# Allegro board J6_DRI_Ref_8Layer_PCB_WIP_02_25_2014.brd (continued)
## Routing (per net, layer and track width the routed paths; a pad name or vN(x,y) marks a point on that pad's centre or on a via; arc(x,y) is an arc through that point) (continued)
VCC_SENSE: length 1.4
  TOP w0.254: v1(131.19,73.02) U45.B3
  BOTTOM w0.203: R549.2 131.19,72.33 v1(131.19,73.02)
VDD_???: length 1.1
  TOP w0.203: U45.L11 124.38,80.62 123.98,81.02 ; 132.78,73.02 132.38,73.42 U45.B1
VDD_CORE: length 41
  TOP w0.102: U52.H14 U52.H13 ; U52.T19 v1(65.53,55.65)
  TOP w0.127: U52.U9 U52.U8
  TOP w0.178: U52.L8 v1(69.55,64.47) U52.L7 ; U52.V8 v1(64.69,64.47) U52.U8 ; U52.N10 v1(68.75,62.83) ; U52.R16 v1(66.32,58.02) U52.T16 ; U52.N13 v1(67.94,59.67) U52.P13 ; U52.V16 v1(64.69,58.07) U52.U16 ; U52.H13 v1(71.91,60.45) ; U52.T13 v1(65.54,59.62) U52.U13 ; U52.J18 v1(71.15,56.44) U52.J17 ; v1(66.35,61.22) U52.R11 ; U52.T19 U52.R19
  TOP w0.203: U52.P12 v1(67.97,61.24) U52.P11 ; 128.78,80.22 U45.K6
  TOP w0.305: v2(65.91,77.24) C487.2 v2(65.91,74.81)
  TOP w1.016: L11.1 131.14,92.34 ; L11.1 129.74,91.26 ; L11.1 132.54,91.26 ; L11.1 131.14,90.18
  BOTTOM w0.203: v1(67.97,61.24) 68.41,60.8 68.81,60.8 C390.2 ; C386.2 67.01,61.88 v1(66.35,61.22) ; C363.2 68.75,62.21 v1(68.75,62.83) ; v1(69.55,64.47) 69.55,65.13 C364.2 ; v1(65.53,55.65) 65.46,55.58 C498.2 ; v1(64.69,64.47) 64.72,64.49 C388.2
  BOTTOM w0.305: v2(72.22,72.21) C456.2 v2(70.18,72.21) ; v2(66.4,72.21) C394.2 v2(64.31,72.21) ; v2(67.23,72.21) C393.2 v2(69.29,72.21) ; v2(75.27,72.21) C395.2 v2(73.22,72.21)
  BOTTOM w0.508: C326.2 131.14,93.07 ; C326.2 131.14,90.78 ; C326.2 132.92,91.93 ; C326.2 129.36,91.93
  vias: v2(129.49,95.2) v2(129.49,94.31) v2(129.49,93.42) v2(130.51,95.2) v2(130.51,94.31) v2(130.51,93.42) v2(132.03,95.2) v2(132.03,94.31) v2(132.03,93.42) v2(133.05,95.2) v2(133.05,94.31) v2(133.05,93.42) v2(133.17,91.26) v2(133.93,95.2) v2(133.93,94.31) v2(133.93,93.42)
VDD_DDR: length 305
  TOP w0.152: U52.AD26 v1(59.13,49.23) ; 61.13,51.25 v1(60.74,50.82) 61.13,50.45 ; U52.W16 v1(63.91,57.23) ; U52.G23 U52.G22 U52.H22
  TOP w0.178: U52.M20 v1(69.55,54.05) ; v1(69.55,54.05) U52.L20 ; v1(69.55,54.05) U52.L21 ; v1(69.55,54.05) U52.M21 ; v1(60.73,53.27) 61.13,52.85 U52.AA22 ; v1(60.73,53.27) U52.AC22 ; v1(60.73,53.27) 61.13,53.65 U52.AA21 ; v1(75.15,50.86) U52.E24 ; U52.H22 v1(71.96,53.27) U52.H21 72.39,53.71 72.39,54.4 U52.H20 ; U52.T24 v1(65.54,50.82) U52.T25
  TOP w0.203: 55.07,48.85 U52.AH27 ; U68.C1 78.23,29.07 v1(77.83,28.67) ; U52.AG20 56.73,54.05 55.83,54.05 55.66,53.89 ; U68.A9 v1(84.23,31.07) ; U65.H2 v1(30.28,27.29) ; v1(78.63,31.05) U68.A2
  TOP w0.229: U52.W27 63.12,48.45 63.12,47.54
  TOP w0.254: U65.C1 29.08,30.9 v1(29.48,31.3) ; v1(42.18,32.09) U66.B2 ; 56.21,46.31 v2(56.16,46.31) ; 56.21,46.31 C138.1 56.97,46.88 57.13,47.04 U52.AG28 ; 56.21,46.31 55.83,45.93 55.07,45.93 ; U69.M9 98.99,21.86 v1(99.39,21.46) 100.07,20.78 C190.1 ; v1(60.65,21.45) U67.M9 ; C559.1 v2(76.63,46.31) ; v2(69.22,26.29) 69.24,26.32 C631.1 ; U66.N9 48.58,23.29 v1(49.38,23.29) 50.72,23.29 C183.1 ; C165.2 v2(68.02,31.57) ; U67.K1 v1(53.45,23.05) ; C204.2 v2(46.69,16.94) ; U66.D2 v1(42.98,29.7) ; U65.H9 v1(35.88,27.29) ; U65.D9 v1(35.88,29.7) U65.E9 ; C162.1 v2(88.49,30.81) ; v1(29.48,25.69) U65.K2 ; U68.M1 v1(77.83,21.46) ; v2(66.75,15.7) C207.2 v2(65.68,14.76) ; v2(62.41,46.18) C139.1 63.2,46.81 63.02,46.99 63.02,47.44 63.12,47.54 ; U66.H9 v1(48.58,27.29) ; U66.C1 41.78,30.9 v1(41.38,31.3) ; U66.E9 v1(48.58,29.7) U66.D9 ; v1(99.39,23.06) 98.99,23.46 U69.K9 ; U69.K1 92.58,23.46 v1(92.18,23.06) ; v1(92.98,27.87) 93.38,27.47 U69.E2 ; U65.N9 35.88,23.29 v1(36.68,23.29) 38.02,23.29 C182.1 ; U65.C9 v1(35.88,30.5) ; v1(78.63,27.87) 79.03,27.47 U68.E2 ; v2(54.64,17.3) C214.1 ; U64.2 6.31,25.36 v2(6.3,25.35) ; C164.2 65.76,32.08 v2(65.89,31.96) ; U68.E9 v1(85.03,27.05) ; C199.1 78.56,19.69 v1(78.56,20.37) ; C137.1 54.18,48.85 v2(54.89,48.85) ; U65.G7 v1(33.48,28.09) ; U65.N1 v1(28.45,22.89) ; U67.G8 v1(59.85,25.47) ; U66.R1 v1(41.06,21.29) ; v2(84.28,17.78) 84.28,18.77 C195.1 ; v1(34.28,32.1) U65.A8 ; v1(98.59,25.46) 98.19,25.86 U69.G8 ; C180.2 v2(67.51,24.84) ; U68.K1 78.23,23.46 v1(77.83,23.06) ; U52.J27 71.93,48.45 71.93,47.7 72.16,47.48 v1(72.16,46.99) ; v1(28.55,32.89) 28.68,32.89 U65.A1 ; C562.1 v2(84.66,46.13) ; C159.1 98.58,31.28 v1(98.58,31.07) U69.A9 ; U67.D7 v1(59.05,28.67) ; v1(29.48,32.09) U65.B2 ; C193.1 38.11,20.89 v1(35.88,20.89) U65.R9 ; U69.D7 v1(97.78,27.87) ; C656.1 v2(76.3,44.91) ; U68.K9 84.64,23.46 v1(85.04,23.06) ; v1(47.78,32.9) U66.A8 ; U67.M1 v1(53.45,21.45) ; C213.1 v2(48.72,17.12) ; C169.1 76.4,29.03 76.77,28.67 v1(77.83,28.67) ; U67.C1 v1(53.45,29.47) ; C196.1 98.3,18.72 v2(98.3,17.78) ; v2(6.17,18.24) C201.2 v2(5.16,19.51) C191.2 v2(5.16,22.18) ; U65.K8 v1(35.08,25.69) ; C160.1 78.31,31.38 v1(78.63,31.05) ; U66.H2 v1(42.98,27.29) ; C181.2 v2(108.79,24.84) ; C211.1 v2(36.07,17.17) ; v1(41.38,32.89) U66.A1 ; C136.1 v2(62.26,44.15) ; C185.1 v2(88.72,22.3) ; 5.41,23.32 v2(6.17,23.32) ; U67.G2 v1(54.25,25.45) ; C205.2 v2(59.41,17.99) ; C176.2 v2(108.79,27.64) ; C548.1 72.82,44.15 v2(73,43.97) ; C210.1 v2(29.87,17.3) ; C208.2 v2(104.03,16.21) ; U67.A9 v1(60.65,31.07) ; C194.1 50.66,20.74 48.74,20.74 v1(48.58,20.89) U66.R9 ; U66.N1 v1(41.06,22.89) ; U69.M1 v1(92.18,21.46) ; v1(86.54,27.79) 86.64,27.69 C171.1 88.44,27.69 v2(88.52,27.76) ; C170.1 90.6,28.43 91.94,28.43 v1(92.18,28.67) 92.58,29.07 U69.C1 ; C184.1 74.6,22.56 v2(74.3,22.25) ; 55.66,53.89 54.91,53.89 v2(54.57,53.55) 54.09,53.55 54.06,53.57 C143.1 ; U66.C9 v1(48.58,30.5) ; C161.1 91.97,32.06 v1(92.98,31.05) U69.A2 ; v2(88.6,20.55) 88.87,20.27 C198.2 ; v2(42.57,17.17) C212.1 ; C203.2 v2(33.86,16.96) ; v1(41.38,28.9) U66.F1 ; C166.2 104.83,30.86 v2(104.52,31.17) ; U66.K8 v1(47.78,25.69) ; U69.G2 v1(92.98,25.47) ; v2(82.85,46.76) 82.85,46.79 82.58,46.51 C657.1 v2(82.58,44.33) ; U68.G8 83.84,25.86 v1(84.24,25.46) ; v2(74.19,19.76) C197.2 75.34,19.76 ; U69.E9 v1(99.39,27.05) ; v1(60.65,23.05) U67.K9 ; C655.1 v2(83.27,47.7) ; U66.G7 v1(46.18,28.09) ; C189.1 86.1,20.4 v1(85.04,21.46) 84.64,21.86 U68.M9 ; U67.B9 v1(60.65,30.27) ; C167.2 v2(109.98,21.11) ; U67.E9 v1(59.85,27.87) ; v2(81.99,48.83) C556.1 ; C557.1 50.75,43.18 50.24,43.69 v2(50.24,43.77) ; C584.1 v2(70.92,46.18) ; v1(28.68,28.9) U65.F1 ; U67.E2 v1(54.25,27.87) ; U67.A2 v1(54.25,31.07) ; U68.G2 v1(78.63,25.47) ; v1(42.18,25.69) U66.K2 ; C175.2 v2(67.51,27.64) ; U65.D2 v1(30.28,30.5) ; C200.1 92.94,19.59 v1(92.94,20.25) ; U69.B9 v1(99.39,29.47) ; 5.41,24.59 v2(6.17,24.59) ; v2(62.97,15.7) C206.2 v2(64.03,14.76) ; v1(84.23,31.07) 84.73,31.57 C158.1 ; U68.B9 v1(85.03,29.47) ; U65.R1 v1(28.36,21.29) ; C209.2 v2(107.8,16.21) ; C589.1 v2(84.71,48.67) ; U68.D7 v1(83.43,27.87)
  TOP w0.305: v2(54.89,48.85) 55.07,48.85 ; v1(100.79,28.15) C172.1 v2(102.77,28.15) ; v1(100.84,31.57) C163.1 v2(102.79,31.57)
  TOP w1.016: 113.5,81.49 L13.1 ; L13.1 114.5,82.81 ; L13.1 115.51,81.49 ; L13.1 114.5,80.16
  BOTTOM w0.203: U68.G2 v1(78.63,25.47) ; U68.G8 v1(84.24,25.46) ; U116.A2 v1(84.23,31.07) ; v1(77.83,30.27) U116.B9 ; v1(63.91,57.23) C508.1 ; U116.E2 v1(83.43,27.87) ; v1(92.98,31.05) U115.A9 ; v1(78.63,31.05) U116.A9 ; U115.E9 v1(92.98,27.87) 93.55,27.87 93.94,28.26 U115.D7 ; U69.K1 92.58,23.46 v1(92.18,23.06) ; v1(77.83,23.06) 78.23,23.46 U68.K1 ; C528.1 71.96,53.29 v1(71.96,53.27) ; U69.G8 v1(98.59,25.46) ; U116.D7 79.59,28.26 79.2,27.87 v1(78.63,27.87) U116.E9 ; U115.B9 v1(92.18,30.27) ; U69.M9 v1(99.39,21.46) ; v1(92.98,25.47) U69.G2 ; U116.C1 v1(85.03,29.47) ; v1(77.83,21.46) U68.M1 ; v1(73.53,51.64) C537.1 ; v1(98.58,31.07) U115.A2 ; U68.K9 v1(85.04,23.06) ; U115.E2 v1(97.78,27.87) ; v1(92.18,21.46) U69.M1 ; U115.C1 v1(99.39,29.47) ; U69.K9 v1(99.39,23.06) ; U68.M9 v1(85.04,21.46)
  BOTTOM w0.254: C644.1 91.11,21.67 91.32,21.46 v1(92.18,21.46) ; v1(35.88,27.29) 36.44,27.29 C622.1 ; v1(59.85,27.87) 60.02,27.87 C614.1 ; C563.1 50.24,43.46 v2(50.24,43.77) ; C671.1 v2(89.56,17.05) ; C666.1 v2(98.55,17.03) ; v2(99.82,13.59) C665.1 v2(99.82,16.03) ; v2(84.84,16.03) C673.1 v2(84.84,13.59) ; v1(35.88,30.5) 36.2,30.81 C598.1 ; C669.1 v2(94.11,17.03) ; C638.1 28.43,22.91 v1(28.45,22.89) ; v2(98.3,17.78) 98.3,18.8 C649.1 ; C679.1 v2(74.02,17.03) ; v1(48.58,29.7) 49.33,29.7 C610.1 ; v2(77.37,16.03) C678.1 v2(77.37,13.59) ; C611.1 35.97,29.61 v1(35.88,29.7) ; C624.1 33.48,27.57 v1(33.48,28.09) ; U116.E9 77.72,27.97 76.43,27.97 75.97,27.51 C616.1 ; C564.1 v2(61.24,42.6) ; C574.1 70.1,54.05 v1(69.55,54.05) ; C677.1 v2(78.82,17.05) ; C602.1 60.82,30.43 v1(60.65,30.27) ; C637.1 v1(86.51,24.34) ; C676.1 v2(80.34,17.07) ; C591.1 54.25,31.69 v1(54.25,31.07) ; v1(54.25,25.45) 54,25.45 53.54,25 C633.1 ; C668.1 v2(95.5,17.03) ; v1(48.58,30.5) 48.9,30.81 C597.1 ; C561.1 72.82,44.15 v2(73,43.97) ; C641.1 52.79,21.45 v1(53.45,21.45) ; C208.2 v2(104.03,16.21) ; C640.1 60.99,21.8 v1(60.65,21.45) ; C613.1 30.28,26.64 v1(30.28,27.29) ; C560.1 v2(47.8,54.51) ; C585.1 92.64,32.57 92.64,31.4 v1(92.98,31.05) ; C643.2 v2(67.51,22.05) ; v2(92.86,16.03) C670.1 v2(92.86,13.59) ; v1(29.48,32.09) 29.49,32.1 C583.1 ; C605.1 28.59,28.81 v1(28.68,28.9) ; C571.1 v2(58.09,41.99) ; U115.E9 92.02,28.02 90.88,28.02 90.37,27.51 C615.1 ; v1(48.58,27.29) 49.14,27.29 C621.1 ; v1(41.06,21.29) 40.42,21.29 C639.1 ; C176.2 v2(108.79,27.64) ; v1(59.85,25.47) 60.46,25.47 C632.1 ; v1(60.73,53.27) 61.48,53.27 C549.1 ; v2(84.28,17.78) 84.28,18.85 C650.1 ; C595.1 91.89,30.56 v1(92.18,30.27) ; v1(77.83,21.46) 76.99,21.46 76.78,21.67 C645.1 ; C651.2 v1(100.91,19.76) ; 52.73,29.42 52.78,29.47 v1(53.45,29.47) ; C590.1 60.86,31.28 v1(60.65,31.07) ; v1(75.15,50.86) 75.24,50.86 C541.1 ; C581.1 99.09,31.57 v1(98.58,31.07) ; v2(72.86,16) C630.1 v2(70.8,16) ; v2(62.97,15.7) C206.2 v2(64.03,14.76) ; C181.2 v2(108.79,24.84) ; C654.2 v2(68.15,17.86) ; C608.1 58.91,28.53 v1(59.05,28.67) ; v2(56.39,44.1) 55.98,44.51 C578.1 ; v2(55.96,40.46) C140.1 v2(57.35,41.48) ; C160.1 78.63,32.27 v1(78.63,31.05) ; C600.1 42.98,30.34 v1(42.98,29.7) ; C612.1 46.18,28.6 v1(46.18,28.09) 46.18,27.57 C623.1 ; v2(63.73,39.32) C576.1 v2(61.65,39.32) ; C674.1 v2(83.52,17.1) ; v1(84.23,31.07) 84.73,31.57 C158.1 ; C588.1 27.92,32.89 v1(28.55,32.89) ; C601.2 v2(108.23,29.01) ; C570.1 v2(50.24,40.67) ; C653.2 v2(109.45,17.86) ; C652.2 v2(88.47,19.76) ; v1(47.78,32.9) 47.78,33.47 C580.1 ; v1(34.28,32.1) 34.17,32.21 C594.1 ; C207.2 v2(66.75,15.7) ; C672.1 v2(88.04,17.05) ; v1(41.38,28.9) 40.6,28.9 C606.1 ; C667.1 v2(97.03,17.03) ; C162.1 v2(88.49,30.81) ; C664.1 v2(103.07,16.47) ; C675.1 v2(81.99,17.07) ; C175.2 v2(67.51,27.64) ; 55.66,35.03 v2(56.34,35.71) ; v2(61.42,36.65) 61.47,36.6 C577.1 63.91,36.6 v2(63.96,36.65) ; C592.1 v2(102.95,30.81) ; C599.2 v2(66.95,31.63) ; C587.1 40.74,32.89 v1(41.38,32.89) ; C180.2 v2(67.51,24.84) ; C569.1 v2(53.98,42.67) ; C572.1 v2(74.75,42.12) ; C609.1 54.25,27.87 v1(54.25,27.87) 54.25,27.26 C625.1 ; C209.2 v2(107.8,16.21) ; v1(77.83,30.27) 77.03,31.07 76.19,31.07 75.68,30.56 C596.1 ; C636.1 v1(100.89,24.34) ; C642.2 v2(108.79,22.05)
  BOTTOM w1.016: C350.2 113.84,83.19 ; C350.2 112.78,81.49 ; C350.2 113.84,79.78 ; C350.2 114.91,81.49
  vias: v2(112.22,83.64) v2(112.22,82.76) v2(112.22,81.49) v2(112.22,80.6) v2(112.22,79.83) v2(113.23,83.64) v2(114.25,83.64)
VDD_DSPEVE_IVA_GPU: length 73
  TOP w0.102: 64.33,61.68 U52.V11
  TOP w0.127: U52.J13 U52.K13
  TOP w0.178: U52.M12 U52.M11 U52.L11 ; U52.V11 U52.U11 U52.U12 ; U52.V14 v1(64.75,59.67) ; U52.V19 U52.V18 v1(64.72,56.44) U52.U18 65.13,55.85 65.11,55.83 65.11,55.48 65.13,55.46 U52.U19 ; v1(63.98,62.05) 64.33,61.68 ; v1(63.98,62.05) U52.V10 ; v1(63.98,62.05) U52.W10 ; v1(63.98,62.05) U52.W11 ; U52.W13 v1(63.14,59.62)
  TOP w0.203: U52.M10 U52.M11 ; U45.K2 131.98,80.22 ; U52.K12 v1(70.35,61.22) ; v1(70.35,61.22) U52.L12 ; v1(70.35,61.22) U52.K11 v1(71.17,62.05) U52.K10 ; v1(70.35,61.22) U52.L11 U52.L10 ; U52.L12 v1(69.55,60.45) ; U52.L12 U52.K13 ; v1(69.55,60.45) U52.M12 ; v1(69.55,60.45) U52.M13
  TOP w0.305: v2(75.76,74.37) C374.2 v2(77.81,74.37) ; v2(71.25,74.75) C453.2 v2(71.25,77.29) ; v2(80.59,66.49) C463.1 v2(80.59,68.04) ; v2(83.65,74.37) C90.2 v2(81.6,74.37) ; v2(50.75,67.4) C108.2 v2(50.75,65.34) ; v2(82.88,69.05) C105.2 v2(82.88,67) ; v2(57.54,74.37) C111.2 v2(55.38,74.37)
  TOP w1.016: L14.1 141.43,82.81 ; L14.1 140.42,81.49 ; L14.1 142.43,81.49 ; L14.1 141.43,80.16 ; L16.1 141.43,78.23 ; L16.1 140.42,76.91 ; L16.1 141.43,75.59 ; L16.1 142.43,76.91
  BOTTOM w0.102: 71.83,63.64 71.57,63.38 71.57,62.46 v1(71.17,62.05)
  BOTTOM w0.127: v1(63.14,59.62) 62.77,59.25 61.91,59.25 C112.1
  BOTTOM w0.203: C495.1 69.4,60.31 v1(69.55,60.45) ; v1(63.98,62.05) 63.98,62.71 C475.1 ; C466.1 64.7,59.62 v1(64.75,59.67) ; C469.1 70.35,60.66 v1(70.35,61.22)
  BOTTOM w0.305: v2(63.37,74.37) C478.2 v2(61.28,74.37) ; v2(58.36,74.37) C483.2 v2(60.41,74.37) ; v2(78.63,74.37) C373.2 v2(80.78,74.37) ; v2(80.59,64.02) C107.1 v2(80.59,65.67) ; v2(53.67,67.58) C473.1 v2(53.67,69.23) ; v2(80.59,70.5) C492.1 v2(80.59,68.85) ; v2(60.86,79.33) C460.1 v2(60.86,76.79) ; v2(82.88,63.77) C465.2 v2(82.88,65.93) ; v2(53.67,61.99) C474.1 v2(53.67,60.34) ; v2(53.67,71.59) C118.1 v2(53.67,70.04) ; v2(63.13,72.21) C372.1 v2(61.48,72.21) ; v2(57.24,72.21) C89.1 v2(55.69,72.21) ; v2(53.67,62.75) C119.1 v2(53.67,64.4)
  vias: v2(140.67,83.14) v2(140.92,79.2) v2(143.46,83.39) v2(143.46,82.5) v2(143.46,80.72) v2(143.46,79.83) v2(143.46,79.07) v2(143.46,78.18) v2(143.46,76.41) v2(143.46,75.39) v2(144.22,83.39) v2(144.22,82.5) v2(144.22,81.61) v2(144.22,80.72) v2(144.22,79.83) v2(144.22,79.07) v2(144.22,78.18) v2(144.22,77.29) v2(144.22,76.41) v2(144.22,75.39)
VDD_MPU: length 83
  TOP w0.102: U52.M15 v1(69.53,58.05) U52.L15 ; U52.L16 v1(69.53,57.25) ; v1(69.53,57.25) U52.M16 ; v1(69.53,57.25) U52.L17 ; v1(69.53,57.25) U52.M17 U52.N17 ; U52.N18 U52.M18 U52.L18
  TOP w0.203: v1(67.94,56.47) U52.N17 ; v1(67.94,56.47) U52.N18 ; v1(67.94,56.47) U52.P17 v1(67.16,56.47) ; v1(67.94,56.47) U52.P18 v1(67.16,56.47) ; v1(69.53,54.87) U52.L19 U52.L18 ; v1(70.35,56.49) 69.93,56.07 U52.L18 ; v1(70.35,56.49) U52.L17 69.53,56.5 ; v1(70.35,56.49) U52.K17 ; v1(70.35,56.49) U52.K18 ; U52.R18 v1(67.16,56.47) ; 69.53,56.5 U52.L18 ; 69.53,56.5 U52.M17
  TOP w0.254: U45.B13 122.78,73.42 v1(122.38,73.02)
  TOP w0.305: v2(90.51,58.5) C96.2 v2(88.46,58.5) ; v2(85.98,69.12) C360.2 v2(85.98,66.68) ; v2(82.37,51.88) C389.1 v2(82.37,53.43) ; v2(88.9,69.93) C356.1 v2(91.59,69.93) ; v2(85.41,58.5) C93.2 v2(87.46,58.5) ; v2(80.59,58.38) C370.2 v2(80.59,56.84) ; v2(80.59,51.88) C365.1 v2(80.59,53.43) ; v2(38.23,26.58) C366.1 v2(38.23,28.23) ; v2(84.65,54.05) C367.2 v2(86.7,54.05)
  TOP w1.016: 114.5,71.02 L17.1 ; L17.1 115.51,72.34 ; L17.1 114.5,73.66 ; L17.1 113.5,72.34 ; L15.1 115.51,76.91 ; L15.1 113.5,76.91 ; L15.1 114.5,75.59 ; L15.1 114.5,78.23
  L3-SIGNAL w0.102: v1(122.38,73.02) 121.23,71.87
  L3-SIGNAL w0.305: 121.23,71.87 120.82,71.45 117.3,71.45 116.79,70.94 v2(116.79,70.31)
  BOTTOM w0.203: v1(67.94,56.47) 68.28,56.14 C391.2 ; C384.1 69.6,57.99 v1(69.53,58.05) ; v1(67.16,56.47) 66.52,55.83 C368.2
  BOTTOM w0.254: v1(70.35,56.49) 70.33,56.47 C385.1
  BOTTOM w0.305: v2(112.09,71.2) 111.84,70.94 R554.1 ; v2(82.37,55.9) C392.2 v2(82.37,54.24) ; v2(82.88,61.86) C387.1 v2(82.88,60.21) ; v2(80.59,54.24) C396.1 v2(80.59,55.9) ; v2(88.46,65.1) C94.2 v2(90.51,65.1) ; v2(85.53,65.1) C92.2 v2(87.59,65.1) ; v2(90.53,62.18) C91.2 v2(88.46,62.18) ; v2(85.48,62.18) C95.2 v2(87.59,62.18) ; v2(84.59,56.97) C359.2 v2(82.44,56.97) ; v2(80.59,61.48) C369.1 v2(80.59,63.13)
  BOTTOM w1.016: 113.84,75.21 C378.2 ; C378.2 113.84,78.62 ; C378.2 114.91,76.91 ; C378.2 112.78,76.91 ; 112.78,72.34 C410.2 ; C410.2 113.84,70.64 ; C410.2 113.84,74.04 ; C410.2 114.91,72.34
  vias: v2(112.09,78.69) v2(112.09,77.55) v2(112.09,76.66) v2(112.09,75.77) v2(112.09,74.88) v2(112.09,73.99) v2(112.09,73.1) v2(112.09,72.09) v2(112.09,70.31) v2(112.09,69.42) v2(112.98,69.42) v2(113.11,74.63) v2(113.18,70.31) v2(113.87,69.42) v2(114.5,70.31) v2(114.88,69.42) v2(115.77,69.42)
VDD_RTC: length 4.9
  TOP w0.178: 61.13,58.45 v1(61.54,58.07)
  TOP w0.203: U45.A5 129.18,71.76 129.43,71.52
  TOP w0.381: C102.2 v2(130.76,69.8) 130.76,70.18 v1(129.74,71.2) 129.43,71.52
  vias: v2(129.74,67.01) v2(130.76,67.01) v2(131.78,67.01)
VDDA_ANA: length 1.7
  TOP w0.254: v1(126.38,74.62) U45.C8
  BOTTOM w0.305: C680.1 v1(126.38,74.62)
VDDA_DEBUG_1V8: length 1.1
  TOP w0.203: U52.N12 68.66,61.22 v1(68.66,61.29) 68.66,61.34 U52.N11
VDDA_HDMI: length 0.6
  TOP w0.178: v1(62.33,56.39) U52.Y17
VDDA_IVA_1V8: length 1.9
  TOP w0.178: U52.R17 v1(66.34,57.28)
  TOP w0.203: U52.R14 v1(67.16,58.83)
  BOTTOM w0.203: v1(67.16,58.83) 67.11,58.88 C497.1
VDDA_MPU_1V8: length 1.9
  TOP w0.203: U52.M14 v1(69.57,58.88) ; U52.N16 v1(68.73,58.07)
  BOTTOM w0.203: C507.2 68.58,57.91 v1(68.73,58.07)
VDDA_PCI_1P8: length 1.9
  TOP w0.178: v1(61.52,56.47) U52.AA17 U52.AA16 ; v1(63.14,58.85) U52.W14
VDDA_PHY_1V8: length 3.8
  TOP w0.178: U52.AA13 v1(61.53,60.46) 61.13,60.86 ; U52.W12 v1(63.14,60.43)
  TOP w0.254: v1(123.98,80.22) U45.K11
  BOTTOM w0.203: C486.1 61.67,60.6 v1(61.53,60.46)
  BOTTOM w0.254: C352.1 v1(123.98,80.22)
VDDA_PLL_1V8: length 7
  TOP w0.203: U45.B5 129.59,73.02 129.59,72.24 129.87,71.96 ; U52.AE16 v1(59.13,57.2) U52.AD16
  TOP w0.381: C103.2 v2(131.78,69.8) 131.78,70.44 v1(130.76,71.45) 130.25,71.96 129.87,71.96
VDDA_RTC: length 4.7
  TOP w0.178: 61.13,60.06 v1(61.54,59.65)
  TOP w0.203: U45.A8 126.75,72.58 126.75,72.04 127.33,71.45
  TOP w0.305: v2(127.71,69.8) 127.33,70.18 127.33,71.45
  TOP w0.381: C431.1 v2(127.71,69.8)
VDDA_SATA_1P8: length 0.5
  TOP w0.178: U52.V13 v1(63.96,59.67)
VDDA_VIDEO_1V8: length 1.7
  TOP w0.203: U52.P15 v1(67.13,58.1) U52.P16 ; U52.P14 v1(67.13,59.6)
VDDR_VREFSTL: length 94.8
  TOP w0.178: U65.M8 34.28,23.29 33.48,23.29 ; 29.72,26.5 30.05,26.5 30.05,26.49 31.08,26.49 ; 43.78,26.49 42.75,26.49 42.75,26.5 42.42,26.5 ; U52.N22 v1(68.69,53.27) ; U66.M8 46.98,23.29 46.18,23.29 ; v1(62.32,55.65) U52.Y18
  TOP w0.203: v1(29.48,27.29) U65.H1 29.48,26.49 29.71,26.49 29.72,26.5 ; U67.E1 v1(53.45,27.87) ; 42.42,26.5 42.41,26.49 42.18,26.49 U66.H1 v1(42.18,27.29)
  TOP w0.254: U67.J8 59.42,24.26 59.02,23.86 58.24,23.86 ; v1(84.24,23.86) 83.84,24.26 U68.J8 ; U69.E1 92.28,27.76 91.34,27.76 v1(91.08,27.51) ; v1(78.63,23.86) 78.63,23.86 78.63,24.46 78.44,24.66 77.17,24.66 ; C177.1 76.48,25.35 76.5,25.38 ; v1(92.98,23.86) 92.98,23.86 92.98,24.46 92.79,24.66 91.52,24.66 ; 56.01,26.26 54.41,26.26 54.25,26.42 54.25,27.06 U67.E1 ; U69.J8 98.19,24.26 v1(98.59,23.86) ; v1(76.73,27.51) 76.99,27.76 77.93,27.76 U68.E1 ; C197.1 76.23,18.24 ; C178.1 90.75,25.61 ; C198.1 90.88,18.75
  TOP w0.305: 67.59,42.88 v2(67.59,43.67)
  TOP w0.508: 58.24,23.86 56.92,23.86 ; 56.92,23.86 56.92,18.04 C205.1 56.97,14.68 ; 56.92,23.86 56.92,25.35 56.01,26.26 ; 32.41,23.29 33.48,23.29 ; 32.41,23.29 32.41,26.01 31.92,26.49 31.08,26.49 ; 32.41,23.29 32.41,18.06 C203.1 32.33,14.76 ; 45.11,23.29 46.18,23.29 ; 45.11,23.29 45.11,26.01 44.62,26.49 43.78,26.49 ; 45.11,23.29 45.11,18.04 C204.1 45.16,14.73
  L3-SIGNAL w0.254: v1(68.69,53.27) 68.29,52.86 67.74,52.86 67.47,52.59 67.47,49.09 68.02,48.54
  L3-SIGNAL w0.381: 68.02,48.54 68.02,44.5 67.59,44.07 v2(67.59,43.67)
  BOTTOM w0.203: U116.J8 v1(78.63,23.86) ; U115.J8 v1(92.98,23.86)
  BOTTOM w0.254: C629.1 86.39,25.35 85.69,24.66 84.43,24.66 84.23,24.46 84.23,23.86 v1(84.24,23.86) ; 100.04,24.66 98.78,24.66 98.58,24.46 98.58,23.86 v1(98.59,23.86) ; U115.E1 99.11,27.59 100.11,27.59 100.15,27.63 v1(100.15,27.61) ; v1(85.72,27.64) 84.81,27.64 U116.E1 ; C651.1 v2(100.91,18.24)
  BOTTOM w0.305: 49.93,55.88 C514.1 49.93,56.79 ; C617.1 v2(55.55,16.11) ; C618.1 43.51,15.95 v2(43.54,15.93)
  vias: v2(76.23,17.86) v2(76.23,17.1) v2(77.11,17.86) v2(77.11,17.1) v2(90.58,17.86) v2(90.58,17.1) v2(91.47,17.86) v2(91.47,17.1)
VDDS_1V8: length 45.7
  TOP w0.102: U52.N8 v1(68.73,63.66) ; v1(64.73,52.45) U52.V22 U52.V21 v1(63.93,54.05) U52.W21 U52.Y21 ; U52.AA19 61.93,55.56 61.93,56.05 U52.AA18
  TOP w0.127: U52.J22 71.55,53.09 71.55,53.64 U52.J21 ; U52.N8 U52.M8 ; U52.R8 U52.P8
  TOP w0.178: U52.M9 v1(69.55,63.65) U52.M8 ; v1(71.95,52.48) U52.J22 ; U52.W17 v1(63.93,56.44) U52.W18 ; U52.Y7 v1(62.33,65.24) ; U52.N21 v1(67.94,53.32) U52.P21 U52.P20 ; U52.AA7 v1(62.36,64.44) ; U52.G18 v1(72.72,56.44) U52.H17 v1(71.93,57.24) ; U52.R8 v1(66.34,63.65) U52.T8 ; v1(62.33,54.86) U52.AA19
  TOP w0.203: 126.38,79.42 126.78,79.02 U45.J8
  TOP w0.305: v2(55.24,79.15) C357.1 v2(55.24,76.71) ; v2(51.08,69.47) C406.1 v2(48.64,69.47) ; v2(51.13,59.95) C382.1 v2(48.59,59.95)
  TOP w0.381: R192.1 v2(123.14,67.01)
  TOP w1.016: L10.1 127.89,91.26 ; L10.1 126.57,92.27 ; L10.1 126.57,90.26 ; L10.1 125.25,91.26
  BOTTOM w0.102: C471.1 73.53,56.37 ; C400.2 61.13,65.51 61.13,65.09 61.37,64.85 61.94,64.85 v1(62.33,65.24) ; v1(62.36,64.44) 62,64.09 61.16,64.09 C399.2
  BOTTOM w0.203: C518.2 63.22,56.44 v1(63.93,56.44) ; v1(72.72,56.44) 73.46,56.44 73.53,56.37 ; v1(66.34,63.65) 65.63,62.94 C461.2 ; C524.1 68.02,53.39 v1(67.94,53.32) ; v1(64.73,52.45) 64.73,53.09 C530.1
  BOTTOM w0.305: v2(53.67,65.17) C371.1 v2(53.67,66.82)
  BOTTOM w0.508: 124.87,91.93 C327.2 ; C327.2 126.57,92.99 ; C327.2 126.57,90.86 ; C327.2 128.27,91.93
  vias: v2(124.54,91.26) v2(124.92,96.73) v2(124.92,95.71) v2(124.92,94.69) v2(124.92,93.68) v2(125.93,96.73) v2(125.93,95.71) v2(125.93,94.69) v2(125.93,93.68) v2(127.08,96.73) v2(127.08,95.71) v2(127.08,94.69) v2(127.08,93.68) v2(128.09,96.73) v2(128.09,95.71) v2(128.09,94.69) v2(128.09,93.68)
VDDSHV: length 39.9
  TOP w0.127: U52.H10 72.33,62.46 72.33,61.66 U52.H11 ; U52.P10 U52.R10 ; U52.J8 U52.K8
  TOP w0.152: U52.G15 U52.H15
  TOP w0.178: U52.R10 v1(66.37,62.08) ; U52.E22 v1(75.19,52.47) U52.D22 ; U52.T4 66.32,66.89 v1(66.32,66.88) U52.T5 ; U52.H8 72.33,63.83 72.33,63.83 72.33,63.52 72.33,63.52 U52.H9 v1(71.95,62.86) U52.H10 ; U52.C24 v1(76.75,50.85) ; v1(75.11,66.88) U52.E5 ; U52.H19 U52.H18 71.97,56.42 v1(71.96,56.42) ; U52.G5 v1(73.56,66.88) U52.G4 ; v1(59.14,66.85) U52.AD5 ; U52.N5 v1(68.72,66.89) U52.N4 ; U52.AD7 v1(59.09,65.24) U52.AE7 ; U52.W4 v1(63.92,66.89) U52.W5 ; U52.D16 v1(75.17,57.22) U52.E16 ; 61.13,64.86 v1(61.51,65.26) 61.13,65.66 ; U52.E10 v1(75.17,62.07) U52.D10 ; U52.U10 v1(64.72,62.08) ; v1(71.95,61.27) U52.H11 ; v1(75.13,68.48) U52.E3 ; v1(57.51,66.86) U52.AF5 ; U52.H16 v1(71.97,58.05) U52.H15 ; v1(66.34,65.26) U52.R7
  TOP w0.203: v1(77.5,66.07) 77.19,65.71 U52.B6 ; U52.B23 U52.C24
  BOTTOM w0.152: C449.1 61.9,66.35 61.9,65.64 v1(61.51,65.26) ; C464.1 59.09,65.52 v1(59.09,65.24)
  BOTTOM w0.203: C484.1 71.97,61.29 v1(71.95,61.27) ; v1(75.11,66.88) 75.11,66.91 C444.2 ; 75.26,61.42 75.17,61.51 v1(75.17,62.07) ; C455.2 77.55,66.12 v1(77.5,66.07) ; v1(63.92,66.89) 64.48,66.89 C443.1 ; v1(75.17,57.22) 75.26,57.13 75.26,56.47 ; C442.1 66.83,67.39 v1(66.32,66.88) ; v1(75.13,68.48) 75.13,68.79 C437.2 ; 69.42,67.26 C445.1 69.09,67.26 v1(68.72,66.89) ; v1(76.75,50.85) 77.39,50.85 C542.2 ; C458.2 74.24,66.19 v1(73.56,66.88) ; v1(57.51,66.86) 56.74,66.86 C454.1 ; v1(66.34,65.26) 66.91,65.26 C457.1 ; v1(75.19,52.47) 75.6,52.88 75.6,53.76 C526.1
  BOTTOM w0.254: C502.1 71.96,58.07 v1(71.97,58.05)
VDDSHV5: length 6.4
  TOP w0.178: U52.V12 v1(64.74,60.45)
  TOP w0.203: 128.78,70.89 128.78,73.03 128.38,73.42 U45.B6
  TOP w0.381: 128.78,70.89 129.74,69.93 v2(129.74,69.8) C101.1
  BOTTOM w0.254: C485.1 64.82,60.53 v1(64.74,60.45)
VDDSHV8: length 2.9
  TOP w0.178: U52.Y8 v1(63.11,63.64) U52.W8
  TOP w0.254: U45.C6 128.38,74.22 v1(128.78,73.82)
  BOTTOM w0.203: C467.1 62.74,63.11 62.74,63.27 v1(63.11,63.64)
H_DCAN1_RX: length 0.6
  TOP w0.102: v1(73.53,55.7) U52.G19
H_DCAN1_TX: length 0.6
  TOP w0.102: U52.G20 v1(72.71,54.85)
H_DDR1_A0: length 117.4
  TOP w0.102: v1(59.16,54.03) U52.AD20
  TOP w0.127: RN4.1 v1(62.39,24.14) ; TP1MC14.1 U67.K3 ; U66.N3 43.79,22.89 43.99,22.69 43.99,22.01 TP1MB19.1 ; TP1MA19.1 31.29,22.01 31.29,22.69 31.09,22.89 U65.N3
  L3-SIGNAL w0.114: TP1MA19.1 31.78,21.01 31.65,20.88 30.2,20.88 29.59,20.27 29.21,20.27 29.06,20.42 29.06,20.7 28.93,20.83 27.82,20.83 27.69,20.7 27.69,20.19 27.57,20.07 27.41,20.07 27.29,20.19 27.29,20.42 27.19,20.53 26.98,20.53 26.88,20.42 26.88,20.19 26.76,20.07 26.59,20.07 26.47,20.19 26.47,20.42 26.37,20.53 26.17,20.53 26.07,20.42 26.07,20.16 25.95,20.04 25.78,20.04 25.66,20.16 25.66,20.42 25.56,20.53 21.79,20.53 20.35,21.97 20.35,28.35 20.65,28.65 20.65,32.77 24.55,36.66 24.69,36.66 24.89,36.46 25.03,36.46 25.18,36.61 25.18,36.75 24.98,36.95 24.98,37.1 25.12,37.24 25.26,37.24 25.46,37.04 25.61,37.04 25.75,37.18 25.75,37.33 25.55,37.53 25.55,37.67 25.7,37.81 25.84,37.81 26.04,37.61 26.18,37.61 26.33,37.76 26.33,37.9 26.13,38.1 26.13,38.25 30.25,42.37 32.33,42.37 35.26,45.29 41.35,45.29 47.83,51.77 52.22,51.77 52.83,52.38 55.22,52.38 56.87,54.03 v1(59.16,54.03) ; v1(62.39,24.14) 60.91,22.67 58.08,22.67 57.69,23.05 TP1MC14.1 55.43,22.64 50.83,22.64 49.5,21.31 44.57,21.31 TP1MB19.1
  BOTTOM w0.127: TP1MA19.1 32.07,21.69 33.6,21.69 34.01,22.1 34.59,22.1 34.98,21.72 36.12,21.72 36.42,21.41 38.43,21.41 39.78,22.76 40.56,22.76 40.82,22.5 42.23,22.5 42.62,22.89 43.14,22.89 43.41,22.62 43.41,22.15 44.16,21.4 TP1MB19.1
H_DDR1_A1: length 113.7
  TOP w0.102: v1(59.93,54.79) U52.AC19
  TOP w0.127: RN4.2 v1(63.02,23.57) ; TP1MC16.1 U67.L7 ; TP1MA20.1 33.44,21.42 U65.P7 ; TP1MB20.1 46.14,21.42 U66.P7
  L3-SIGNAL w0.114: v1(63.02,23.57) 62.63,23.57 60.93,21.87 58.64,21.87 TP1MC16.1 54.2,22.25 53.82,21.87 51.86,21.87 50.5,20.51 46.4,20.51 TP1MB20.1 42.8,20.91 42.42,21.28 41.95,21.28 41.36,20.69 40.32,20.69 40.3,20.72 38.06,20.72 37.05,19.71 34.5,19.71 TP1MA20.1 32.79,20.4 30.4,20.4 29.69,19.69 25.04,19.69 24.93,19.8 24.93,19.94 24.8,20.07 24.6,20.07 24.47,19.94 24.47,19.8 24.36,19.69 24.12,19.69 24,19.8 24,19.93 23.89,20.04 23.66,20.04 23.55,19.93 23.55,19.8 23.43,19.69 23.2,19.69 23.09,19.8 23.09,19.93 22.97,20.04 22.75,20.04 22.63,19.93 22.63,19.8 22.52,19.69 22.05,19.69 19.96,21.77 19.96,32.59 30.12,42.75 32.08,42.75 35,45.67 41.1,45.67 47.57,52.15 52.04,52.15 52.58,52.68 55.04,52.68 56.69,54.33 58.7,54.33 59.15,54.79 v1(59.93,54.79)
H_DDR1_A2: length 122.7
  TOP w0.102: v1(60.71,54.86) U52.AC20
  TOP w0.127: U67.L3 56.31,21.8 56.31,19.41 TP1MC26.1 ; RN6.4 v1(63.02,19.07) ; U65.P3 30.91,21.87 30.91,21.87 31.18,21.6 31.18,20.82 31.6,20.4 31.6,19.7 31.48,19.59 TP1MA27.1 ; U66.P3 43.61,21.87 43.61,21.87 43.88,21.6 43.88,20.82 44.3,20.4 44.3,19.7 44.18,19.59 TP1MB27.1
  L3-SIGNAL w0.102: 60.33,54.2 60.33,53.84 60.07,53.58 59.72,53.58 59.48,53.34 59.48,53 59.31,52.84
  L3-SIGNAL w0.114: v2(21.74,21.54) 22.05,21.85 22.05,22 21.11,22.94 21.11,27.84 21.41,28.15 21.41,32.51 24.43,35.54 25.22,35.54 29.87,40.19 29.87,40.39 30.11,40.63 30.46,40.63 30.77,40.32 30.92,40.32 31.06,40.46 31.06,40.6 30.64,41.02 30.64,41.19 30.76,41.31 30.93,41.31 31.35,40.89 31.52,40.89 31.65,41.02 31.65,41.48 31.78,41.61 32.08,41.61 32.31,41.38 32.61,41.38 35.76,44.53 41.86,44.53 48.39,51.06 55.32,51.06 56.86,52.59 57.85,52.59 58.09,52.84 59.31,52.84 ; v1(60.71,54.86) 60.59,54.74 60.59,54.47 60.33,54.2 ; v1(63.02,19.07) 62.96,19 TP1MC26.1 54.59,19 53.99,18.4 45.21,18.4 45.11,18.49 TP1MB27.1
  BOTTOM w0.127: TP1MB27.1 43.37,17.68 39.83,17.68 39.7,17.81 39.21,17.81 39.08,17.68 35.66,17.68 35.53,17.55 35.53,17.45 35.41,17.33 34.62,17.33 34.49,17.45 34.49,17.55 34.37,17.68 33.07,17.68 32.96,17.78 32.96,17.94 32.84,18.06 32.68,18.06 32.56,17.94 32.56,17.78 32.46,17.68 32.13,17.68 32,17.81 32,18.37 31.88,18.49 TP1MA27.1 30.82,17.83 24.56,17.83 21.74,20.65 v2(21.74,21.54)
H_DDR1_A3: length 128.9
  TOP w0.102: v1(61.53,54.83) 61.13,55.25
  TOP w0.127: TP1MC13.1 U67.K2 ; TP1MA14.1 29.76,22.49 29.57,22.3 29.41,22.3 29.27,22.44 29.27,22.58 29.58,22.89 U65.N2 ; TP1MB14.1 42.46,22.49 42.27,22.3 42.11,22.3 41.97,22.44 41.97,22.58 42.28,22.89 U66.N2
  L3-SIGNAL w0.114: v1(63.02,24.56) 61.95,24.56 60.83,23.45 54.64,23.45 TP1MC13.1 53.86,23.44 52.01,23.44 51.66,23.09 50.88,23.09 50.12,22.34 49.08,22.34 48.85,22.11 45.4,22.11 44.7,22.81 43.7,22.81 43.38,22.49 TP1MB14.1 42.74,22.74 41.51,22.74 41.28,22.51 40.67,22.51 40.49,22.68 40.49,22.94 40.18,23.24 37.8,23.24 37.59,23.04 37.59,22.58 37.39,22.38 36.35,22.38 36.04,22.08 35.46,22.08 35.03,22.51 33.72,22.51 33.36,22.15 32.87,22.15 32.11,22.91 31.06,22.91 30.64,22.49 TP1MA14.1 29.83,22.49 29.73,22.39 29.73,21.77 29.63,21.67 29.42,21.67 29.32,21.77 29.32,22.39 29.22,22.49 28.14,22.49 27.95,22.68 26.87,22.68 26.75,22.56 26.75,21.54 26.62,21.41 26.39,21.41 26.31,21.49 26.31,22.31 26.2,22.43 26.03,22.43 25.91,22.31 25.91,21.52 25.81,21.41 25.6,21.41 25.5,21.52 25.5,21.95 25.4,22.05 25.2,22.05 25.1,21.95 25.1,21.52 24.99,21.41 24.71,21.41 24.46,21.67 24.46,21.92 24.84,22.3 24.84,23.07 24.71,23.19 23.7,23.19 23.57,23.07 23.57,22.68 23.7,22.56 v2(24.28,22.56)
  BOTTOM w0.102: v1(61.53,54.83) 61.09,55.27 60.6,55.27 60.38,55.5 60.38,55.81 60.12,56.06 59.77,56.06
  BOTTOM w0.127: 59.77,56.06 59.54,55.83 59.54,55.4 58.47,54.33 56.87,54.33 55.41,52.87 49.84,52.87 44.92,47.96 39.57,47.96 39.32,48.21 35.84,48.21 24.28,36.65 24.28,30.53 24.18,30.43 22.94,30.43 22.68,30.69 22.68,31.07 22.56,31.19 21.92,31.19 21.79,31.07 21.79,30.46 21.89,30.36 22.31,30.36 22.43,30.24 22.43,30.07 22.31,29.95 21.89,29.95 21.79,29.85 21.79,29.64 21.89,29.54 22.44,29.54 22.56,29.42 22.56,29.26 22.44,29.14 21.89,29.14 21.79,29.03 21.79,26.88 21.67,26.75 21.35,26.75 21.23,26.64 21.23,26.48 21.35,26.37 21.67,26.37 22.05,25.99 22.3,25.99 22.43,26.11 22.43,26.65 22.56,26.77 22.77,26.77 22.89,26.65 22.89,25.78 23.19,25.48 23.44,25.48 23.57,25.35 23.57,25.1 24.28,24.39 v2(24.28,22.56) ; RN15.4 63.9,24.14 63.47,24.56 v1(63.02,24.56)
H_DDR1_A4: length 129.5
  TOP w0.102: v1(57.53,53.3) U52.AF21
  TOP w0.127: TP1MB16.1 48.98,21.69 47.78,21.69 U66.P8 ; RN4.3 61.8,23.07 60.99,22.25 TP1MC17.1 U67.L8 ; TP1MA16.1 36.28,21.69 35.08,21.69 U65.P8
  BOTTOM w0.127: TP1MC17.1 58.64,22.66 57.45,22.66 57.3,22.51 57.3,21.79 57.18,21.67 57.02,21.67 56.9,21.79 56.9,22.51 56.78,22.63 56.61,22.63 56.49,22.51 56.49,21.86 56.37,21.74 56.2,21.74 56.08,21.86 56.08,22.15 55.98,22.25 55.78,22.25 55.68,22.15 55.68,21.86 55.56,21.74 55.39,21.74 55.27,21.86 55.27,22.15 55.17,22.25 54.97,22.25 54.87,22.15 54.87,21.84 54.75,21.72 54.58,21.72 54.46,21.84 54.46,22.15 54.36,22.25 54.15,22.25 54.05,22.15 54.05,21.97 53.94,21.86 53.15,21.86 52.81,22.2 50.24,22.2 49.99,21.95 TP1MB16.1 48.96,21.67 48.13,21.67 47.68,22.13 46.43,22.13 46.25,21.95 44.2,21.95 43.84,22.3 43.84,22.79 43.35,23.28 42.37,23.28 42.19,23.09 41.53,23.09 41.33,23.29 39.78,23.29 38.25,21.77 37.24,21.77 37.06,21.95 TP1MA16.1 36.39,22.1 35.51,22.1 35.13,22.48 33.79,22.48 33.43,22.13 32.51,22.13 32.33,22.3 32.33,22.55 31.6,23.28 31.45,23.28 31.24,23.07 31.06,23.07 30.85,23.28 29.62,23.28 29.29,22.94 28.96,22.94 28.78,23.12 28.78,23.4 28.6,23.57 25.86,23.57 25.74,23.69 25.74,23.84 25.86,23.95 26.62,23.95 26.74,24.07 26.74,24.22 26.62,24.34 25.86,24.34 25.73,24.46 25.73,24.97 25.6,25.1 25.22,25.1 25.1,25.22 25.1,25.37 24.99,25.47 24.82,25.47 24.71,25.57 24.71,25.77 24.82,25.87 24.99,25.87 25.1,25.98 25.1,26.18 24.99,26.28 24.82,26.28 24.71,26.38 24.71,26.59 24.82,26.69 24.99,26.69 25.1,26.79 25.1,26.99 24.99,27.09 24.82,27.09 24.71,27.2 24.71,27.4 24.82,27.5 24.99,27.5 25.1,27.6 25.1,27.84 24.97,27.97 24.84,27.97 24.71,28.09 24.71,28.78 24.84,28.91 25.32,28.91 25.81,29.39 25.81,35.59 25.98,35.77 26.24,35.77 26.75,36.27 26.75,36.53 26.62,36.65 26.62,37.01 30.53,40.92 30.73,40.92 31.32,40.34 31.57,40.34 31.76,40.53 31.76,40.67 31.41,41.02 31.41,41.17 31.55,41.31 31.7,41.31 32.05,40.96 32.19,40.96 32.33,41.1 32.97,41.1 33.1,41.23 33.1,42.62 33.4,42.93 33.4,43.32 33.95,43.87 33.95,44.25 34.05,44.35 34.25,44.35 34.35,44.25 34.35,43.63 34.47,43.51 34.64,43.51 34.76,43.63 34.76,44.54 34.88,44.66 35.05,44.66 35.16,44.54 35.16,43.63 35.28,43.51 35.45,43.51 35.57,43.63 35.57,44.54 35.69,44.66 35.86,44.66 35.98,44.54 35.98,43.63 36.1,43.51 36.26,43.51 36.38,43.63 36.38,44.54 36.5,44.66 36.67,44.66 36.79,44.54 36.79,43.63 36.91,43.51 37.08,43.51 37.2,43.63 37.2,44.54 37.32,44.66 37.48,44.66 37.6,44.54 37.6,43.63 37.72,43.51 37.89,43.51 38.01,43.63 38.01,44.54 38.13,44.66 38.3,44.66 38.42,44.54 38.42,43.63 38.53,43.51 38.7,43.51 38.82,43.63 38.82,44.54 38.94,44.66 39.11,44.66 39.23,44.54 39.23,43.64 39.36,43.51 39.6,43.51 39.72,43.39 39.72,43.17 39.84,43.06 40.01,43.06 40.13,43.17 40.13,44.16 40.25,44.27 40.42,44.27 40.54,44.16 40.54,43.12 40.66,43 40.82,43 40.94,43.12 40.94,44.16 41.06,44.27 41.23,44.27 41.35,44.16 41.35,43.61 41.45,43.51 41.65,43.51 41.95,43.81 42.43,43.81 50.06,51.44 53.43,51.44 53.84,51.84 55.6,51.84 57.06,53.3 v1(57.53,53.3)
H_DDR1_A5: length 138.1
  TOP w0.127: U65.P2 29.76,21.97 29.46,21.97 29.34,21.84 29.34,21.66 29.49,21.5 29.49,20.9 TP1MA21.1 28.64,20.89 28.14,20.4 28.14,19.21 28.03,19.1 27.87,19.1 27.76,19.21 27.76,20.55 27.66,20.65 27.48,20.65 27.38,20.55 27.38,19.23 27.28,19.13 27.1,19.13 27,19.23 27,20.24 26.9,20.35 26.7,20.35 26.59,20.24 26.59,19.74 26.49,19.64 26.29,19.64 26.19,19.74 26.19,20.24 26.09,20.35 25.34,20.35 25.22,20.46 25.22,20.63 25.34,20.75 26.59,20.75 26.7,20.85 26.7,21.06 26.59,21.16 25.34,21.16 25.22,21.28 25.22,21.45 25.34,21.56 26.59,21.56 26.7,21.67 26.7,21.87 26.59,21.97 25.34,21.97 25.22,22.09 25.22,22.26 25.34,22.38 26.59,22.38 26.7,22.48 26.7,22.99 26.11,23.57 26.11,24.11 26.01,24.21 24.95,24.21 24.84,24.32 24.84,24.48 24.95,24.59 26.01,24.59 26.11,24.69 26.11,24.87 26.01,24.97 25.07,24.97 24.97,25.07 24.97,25.25 25.07,25.35 26.01,25.35 26.11,25.45 26.11,25.63 26.01,25.73 25.02,25.73 24.92,25.83 24.92,30.61 24.21,31.32 24.21,32.06 24.1,32.16 23.8,32.16 23.7,32.26 23.7,32.47 23.8,32.57 24.1,32.57 24.21,32.67 24.21,33.69 24.1,33.79 23.82,33.79 23.7,33.91 23.7,34.08 23.82,34.2 24.1,34.2 24.21,34.3 24.21,34.5 24.1,34.6 23.82,34.6 23.7,34.72 23.7,34.89 23.82,35.01 24.1,35.01 24.21,35.11 24.21,35.34 24.1,35.44 23.82,35.44 23.7,35.56 23.7,35.73 23.82,35.85 24.1,35.85 24.21,35.95 24.21,36.65 30.05,42.5 31.03,42.5 31.13,42.6 31.13,43.54 31.23,43.64 31.44,43.64 31.54,43.54 31.54,42.62 31.66,42.5 31.83,42.5 31.95,42.62 31.95,43.87 32.25,44.16 32.25,44.3 32.06,44.49 32.06,44.63 32.2,44.78 32.34,44.78 32.63,44.49 32.8,44.49 32.92,44.61 32.92,44.78 32.63,45.06 32.63,45.21 32.78,45.35 32.92,45.35 33.11,45.16 33.25,45.16 33.51,45.42 33.99,45.42 34.09,45.52 34.09,45.81 34.21,45.93 34.38,45.93 34.5,45.81 34.5,45.52 34.6,45.42 34.8,45.42 34.9,45.52 34.9,45.81 35.02,45.93 35.19,45.93 35.31,45.81 35.31,45.52 35.41,45.42 35.61,45.42 35.72,45.52 35.72,45.81 35.83,45.93 36,45.93 36.12,45.81 36.12,45.52 36.22,45.42 36.43,45.42 36.53,45.52 36.53,45.81 36.65,45.93 36.82,45.93 36.93,45.81 36.93,45.52 37.04,45.42 37.24,45.42 37.34,45.52 37.34,45.81 37.46,45.93 37.63,45.93 37.75,45.81 37.75,45.52 37.85,45.42 38.05,45.42 38.15,45.52 38.15,45.81 38.27,45.93 38.44,45.93 38.56,45.81 38.56,45.52 38.66,45.42 38.87,45.42 38.97,45.52 38.97,45.81 39.09,45.93 39.25,45.93 39.37,45.81 39.37,45.52 39.47,45.42 39.68,45.42 39.78,45.52 39.78,45.81 39.9,45.93 40.07,45.93 40.19,45.81 40.19,45.52 40.29,45.42 40.49,45.42 40.59,45.52 40.59,45.93 40.71,46.05 40.88,46.05 41,45.93 41,45.31 41.12,45.19 41.29,45.19 41.41,45.31 41.41,45.95 41.51,46.05 41.71,46.05 41.81,45.95 41.81,45.52 41.91,45.42 42.57,45.42 49.71,52.56 55.6,52.56 55.9,52.85 U52.AH22 ; TP1MC18.1 54.25,22.26 U67.L2 ; U66.P2 42.46,21.97 42.16,21.97 42.04,21.84 42.04,21.66 42.19,21.5 42.19,20.9 TP1MB21.1 ; RN4.4 v1(63.02,22.5)
  L3-SIGNAL w0.114: v1(63.02,22.5) 62.32,22.5 60.89,21.07 57.68,21.07 56.9,21.84 54.63,21.84 TP1MC18.1 53.85,21.06 51.59,21.06 50.23,19.71 46.77,19.71 45.97,20.5 42.58,20.5 TP1MB21.1
  BOTTOM w0.127: TP1MB21.1 41.88,20.6 41.88,20.02 41.57,19.7 40.96,19.7 40.61,20.04 39.22,20.04 38.96,20.3 37.49,20.3 37.36,20.42 36.98,20.42 36.75,20.2 36.4,20.2 36.11,20.49 35.55,20.49 35.26,20.78 34.49,20.78 34.23,20.51 31.56,20.51 31.18,20.89 30.57,20.89 30.28,21.19 29.78,21.19 TP1MA21.1
H_DDR1_A6: length 129.2
  TOP w0.127: TP1MC21.1 U67.M8 ; v1(27.58,21.29) 27.58,21.91 27.48,22.01 27.23,22.01 27.13,22.11 27.13,22.32 27.23,22.42 27.48,22.42 27.58,22.52 27.58,23.34 27.69,23.44 28.04,23.44 28.14,23.54 28.14,23.75 28.04,23.85 27.69,23.85 27.58,23.95 27.58,24.15 27.69,24.26 28.04,24.26 28.14,24.36 28.14,24.56 28.04,24.66 27.69,24.66 27.58,24.76 27.58,24.97 27.69,25.07 28.15,25.07 28.27,25.19 28.27,25.36 28.15,25.47 27.69,25.47 27.58,25.58 27.58,25.78 27.69,25.88 28.15,25.88 28.27,26 28.27,26.17 28.15,26.29 27.69,26.29 27.58,26.39 27.58,26.62 27.41,26.8 27.41,26.94 27.54,27.08 27.54,27.22 27.4,27.37 27.25,27.37 27.12,27.23 26.82,27.23 26.04,28.02 26.04,34.55 26.86,35.37 26.86,35.52 26.26,36.12 26.26,36.29 26.37,36.41 26.54,36.41 27.26,35.69 27.43,35.69 27.55,35.81 27.55,35.98 26.75,36.77 26.75,36.92 26.9,37.06 27.04,37.06 27.72,36.38 27.87,36.38 28.01,36.52 28.01,36.67 27.33,37.35 27.33,37.49 27.47,37.64 27.62,37.64 28.41,36.84 28.58,36.84 28.7,36.96 28.7,37.13 27.9,37.92 27.9,38.07 28.05,38.21 28.19,38.21 28.87,37.53 29.02,37.53 29.16,37.67 29.16,37.82 28.48,38.5 28.48,38.64 28.62,38.79 28.77,38.79 29.63,37.93 29.8,37.93 29.91,38.05 29.91,38.21 29.05,39.07 29.05,39.22 29.2,39.36 29.34,39.36 30.02,38.68 30.17,38.68 30.31,38.82 30.31,38.97 29.63,39.65 29.63,39.79 29.77,39.94 29.92,39.94 30.84,39.01 31.01,39.01 31.13,39.13 31.13,39.3 30.2,40.22 30.2,40.37 30.35,40.51 30.49,40.51 31.23,39.78 31.39,39.78 31.51,39.9 31.51,40.07 30.78,40.8 30.78,40.94 30.92,41.09 31.07,41.09 31.94,40.21 32.84,40.21 33.86,41.23 38.43,41.23 38.81,40.85 39.52,40.85 47.09,48.41 47.23,48.41 47.37,48.28 47.51,48.28 47.66,48.42 47.66,48.56 47.52,48.7 47.52,48.84 47.66,48.99 47.81,48.99 47.94,48.85 48.09,48.85 48.23,48.99 48.23,49.14 48.09,49.27 48.09,49.42 48.24,49.56 48.38,49.56 48.52,49.43 48.66,49.43 48.81,49.57 48.81,49.71 48.67,49.85 48.67,49.99 48.81,50.14 48.96,50.14 49.09,50 49.24,50 49.38,50.14 49.38,50.29 49.24,50.42 49.24,50.57 49.56,50.88 49.93,50.88 50.04,50.98 50.04,51.16 50.14,51.26 50.34,51.26 50.44,51.16 50.44,50.98 50.54,50.88 50.75,50.88 50.85,50.98 50.85,51.16 50.95,51.26 51.15,51.26 51.25,51.16 51.25,50.98 51.36,50.88 51.56,50.88 51.66,50.98 51.66,51.16 51.76,51.26 51.97,51.26 52.07,51.16 52.07,50.98 52.19,50.85 53.74,50.85 54.35,51.46 55.8,51.46 55.98,51.64 56.72,51.64 U52.AG23 ; U66.R8 47.78,20.89 TP1MB22.1 ; U65.R8 35.08,20.89 TP1MA22.1
  BOTTOM w0.127: RN17.3 63.58,20.14 63.18,20.54 62.83,20.54 62.46,20.17 60.33,20.17 TP1MC21.1 58.01,20.41 57.79,20.41 57.69,20.31 57.69,19.97 57.59,19.87 57.39,19.87 57.29,19.97 57.29,20.31 57.19,20.41 56.98,20.41 56.88,20.31 56.88,19.97 56.78,19.87 56.58,19.87 56.47,19.97 56.47,20.31 56.37,20.41 55.66,20.41 55.3,20.04 54.71,20.04 54.51,20.25 54.08,20.25 53.63,19.8 53.12,19.8 52.83,20.09 52.63,20.09 52.53,19.99 52.53,19.81 52.43,19.71 52.22,19.71 52.12,19.81 52.12,19.99 52.02,20.09 49.15,20.09 48.74,19.69 48.19,19.69 TP1MB22.1 47.17,20.7 46.46,20.7 46.27,20.51 45.2,20.51 45.09,20.4 42.98,20.4 41.94,19.36 40.08,19.36 39.67,19.76 39.32,19.76 39.04,19.48 38.61,19.48 38.28,19.81 37.49,19.81 37.11,19.43 35.28,19.43 35.08,19.63 TP1MA22.1 34.57,20.09 34.47,20.2 33.12,20.2 32.99,20.07 31.52,20.07 31.12,20.47 29.13,20.47 28.93,20.68 28.2,20.68 v1(27.58,21.29)
H_DDR1_A7: length 107.9
  TOP w0.102: v1(59.1,53.24) U52.AE21
  TOP w0.127: U66.R2 TP1MB17.1 ; U67.M2 55.05,21.46 TP1MC22.1 ; RN6.2 v1(63.02,20.14) ; U65.R2 TP1MA17.1
  L3-SIGNAL w0.114: TP1MC22.1 56.31,20.65 57.5,19.47 60.99,19.47 61.67,20.14 v1(63.02,20.14)
  BOTTOM w0.127: TP1MC22.1 54.01,20.65 53.61,20.25 53.24,20.25 52.97,20.51 50.46,20.51 50.36,20.61 50.36,21.04 50.24,21.16 50.07,21.16 49.95,21.04 49.95,20.61 49.85,20.51 49.65,20.51 49.55,20.61 49.55,20.83 49.45,20.93 49.24,20.93 49.14,20.83 49.14,20.61 49.03,20.5 48.11,20.5 47.42,21.19 46.53,21.19 46.15,21.57 45.57,21.57 44.91,20.91 43.77,20.91 TP1MB17.1 42.7,21.41 42.42,21.41 42.09,21.74 41.73,21.74 41.53,21.54 41.53,21.03 41.07,20.58 39.4,20.58 39.17,20.8 36.54,20.8 36.05,21.29 35.45,21.29 35.35,21.19 34.29,21.19 34.16,21.06 33.81,21.06 33.54,21.33 32.85,21.33 32.46,20.93 31.6,20.93 31.23,21.3 30.68,21.3 TP1MA17.1 30.05,21.92 29.64,21.92 29.33,21.61 29.33,21.39 29.23,21.29 29.03,21.29 28.93,21.39 28.93,21.61 28.84,21.69 28.07,21.69 27.91,21.85 25.61,21.85 24.79,22.66 24.79,24.39 23.95,25.22 23.95,25.73 23.32,26.37 23.32,27 22.81,27.51 22.81,28.02 23.44,28.65 23.83,28.65 23.95,28.78 23.95,29.54 24.08,29.67 24.97,29.67 25.04,29.75 25.04,36.4 30.53,41.89 31.09,41.89 31.82,42.62 31.82,43.17 34.19,45.54 34.75,45.54 35.89,46.69 36.64,46.69 36.88,46.92 38.32,46.92 38.89,46.35 42.57,46.35 42.77,46.15 43.91,46.15 50.11,52.35 55.61,52.35 57.01,53.75 58.58,53.75 v1(59.1,53.24)
H_DDR1_A8: length 116.1
  TOP w0.102: U52.AF22 v1(58.34,53.23)
  TOP w0.127: TP1MC25.1 59.45,20.26 U67.N8 ; U65.T8 TP1MA26.1 ; U66.T8 TP1MB26.1
  L3-SIGNAL w0.102: 56.63,52.92 57.69,52.92 58,53.23 v1(58.34,53.23)
  L3-SIGNAL w0.114: 56.63,52.92 55.09,51.39 48.08,51.39 41.61,44.91 35.51,44.91 32.59,41.99 30.86,41.99 30.41,41.54 30.25,41.54 30.17,41.62 30.01,41.62 29.85,41.46 29.85,41.29 29.92,41.21 29.92,41.05 29.75,40.88 29.59,40.88 29.53,40.94 29.38,40.94 29.24,40.8 29.24,40.65 29.41,40.48 29.41,40.34 29.27,40.19 29.12,40.19 28.95,40.37 28.81,40.37 28.66,40.22 28.66,40.08 28.84,39.9 28.84,39.76 28.69,39.62 28.55,39.62 28.38,39.79 28.23,39.79 28.09,39.65 28.09,39.5 28.26,39.33 28.26,39.19 28.12,39.04 27.97,39.04 27.8,39.22 27.66,39.22 27.51,39.07 27.51,38.93 27.69,38.75 27.69,38.61 27.54,38.47 27.4,38.47 27.23,38.64 27.08,38.64 26.75,38.31 26.75,37.67 24.99,35.92 24.31,35.92 21.03,32.64 21.03,28.4 20.73,28.09 20.73,22.56 v2(21.11,22.18)
  BOTTOM w0.127: RN17.1 63.59,19.07 63.14,18.62 60.28,18.62 TP1MC25.1 58.61,19.41 58.61,19.27 58.82,19.06 58.82,18.89 58.7,18.77 58.53,18.77 58.32,18.98 58.18,18.98 58.04,18.84 58.04,18.69 58.23,18.5 58.23,18.36 58.09,18.21 57.94,18.21 57.75,18.41 57.6,18.41 57.36,18.16 47.6,18.16 TP1MB26.1 46.13,18.37 45.14,18.37 44.58,18.93 43.94,18.93 43.23,18.21 39.93,18.21 39.7,18.44 39.19,18.44 39.04,18.29 35.33,18.29 35.2,18.16 35.2,18.04 35.08,17.91 34.87,17.91 34.75,18.04 34.75,18.34 34.62,18.47 34.19,18.47 34.06,18.6 TP1MA26.1 33.57,19 33.25,18.68 32.45,18.68 32.13,19 31.34,19 30.58,18.24 24.92,18.24 22.38,20.78 22.38,21.54 21.74,22.18 v2(21.11,22.18)
H_DDR1_A9: length 116.8
  TOP w0.102: v1(58.35,52.44) U52.AE22
  TOP w0.127: RN6.1 v1(62.39,20.71) ; TP1MB25.1 42.98,20.09 42.98,20.89 U66.R3 ; TP1MA25.1 30.28,20.09 30.28,20.89 U65.R3 ; TP1MC19.1 U67.M3
  L3-SIGNAL w0.102: v1(58.35,52.44) 58.24,52.33 57.12,52.33
  L3-SIGNAL w0.114: v1(62.39,20.71) 61.43,20.71 60.98,20.27 57.64,20.27 56.45,21.45 TP1MC19.1 55.63,21.24 54.84,21.24 53.75,20.14 51.05,20.14 50.37,19.46 46.63,19.46 46.55,19.38 43.32,19.38 TP1MB25.1 42.58,19.57 42.06,19.05 40.79,19.05 40.34,19.51 39.78,19.51 39.42,19.87 39.01,19.87 38.63,19.48 38.63,19.03 38.15,18.54 37.85,18.54 37.62,18.77 37.26,18.77 37.03,18.54 32.94,18.54 32.23,19.26 31.78,19.26 31.47,18.95 31.05,18.95 TP1MA25.1 ; 57.12,52.33 55.55,50.75 48.72,50.75 42.11,44.15 36.02,44.15 32.52,40.65 32.38,40.65 32.19,40.84 32.02,40.84 31.9,40.72 31.9,40.55 32.13,40.32 32.13,40.16 32.01,40.04 31.84,40.04 31.63,40.25 31.48,40.25 31.13,39.89 30.86,39.89 30.73,39.77 30.73,39.52 30.61,39.4 30.38,39.4 30.11,39.66 29.93,39.66 29.78,39.51 29.78,39.33 30.04,39.07 30.04,38.93 29.89,38.79 29.75,38.79 29.49,39.05 29.32,39.05 29.2,38.93 29.2,38.76 29.46,38.5 29.46,38.36 29.32,38.21 29.17,38.21 28.91,38.47 28.74,38.47 28.62,38.35 28.62,38.19 28.89,37.92 28.89,37.78 28.74,37.64 28.6,37.64 28.35,37.89 28.18,37.89 28.06,37.77 28.06,37.6 28.31,37.35 28.31,37.2 28.17,37.06 28.02,37.06 27.76,37.32 27.59,37.32 27.47,37.2 27.47,37.04 27.74,36.77 27.74,36.63 27.59,36.49 27.45,36.49 27.21,36.72 27.07,36.72 26.92,36.58 26.92,36.44 27.16,36.2 27.16,36.05 27.02,35.91 26.87,35.91 26.64,36.15 26.49,36.15 26.35,36 26.35,35.86 26.59,35.62 26.59,35.48 26.44,35.34 26.3,35.34 26.06,35.57 25.92,35.57 25.48,35.13 24.54,35.13 21.79,32.39 21.79,27.89 21.49,27.59 21.49,23.19 22.77,21.91 22.77,21.77 22.24,21.23 22.24,21.07 22.36,20.95 22.53,20.95 23.06,21.48 23.2,21.48 v2(23.52,21.16)
  BOTTOM w0.127: TP1MA25.1 29.94,19.57 29.82,19.69 29.54,19.69 29.13,19.28 25.4,19.28 24.97,19.71 24.97,20.02 24.8,20.18 24.5,20.18 v2(23.52,21.16)
H_DDR1_A10: length 125.1
  TOP w0.102: U52.AD21 v1(59.94,54)
  TOP w0.127: TP1MC6.1 58.25,25.45 U67.H7 ; U65.L7 33.53,24.84 33.3,24.84 33.17,24.72 TP1MA8.1 ; TP1MB8.1 45.87,24.72 46,24.84 46.23,24.84 U66.L7
  L3-SIGNAL w0.114: v2(23.44,29.16) 23.44,28.78 23.57,28.65 23.99,28.65 24.1,28.53 24.1,28.37 23.99,28.25 23.52,28.25 23.39,28.12 23.39,26.68 23.5,26.58 24.36,26.58 24.46,26.48 24.46,26.28 24.36,26.18 23.5,26.18 23.39,26.08 23.39,25.87 23.5,25.77 24.47,25.77 24.59,25.65 24.59,25.48 24.47,25.36 23.5,25.36 23.39,25.26 23.39,24.84 23.77,24.46 24.09,24.46 24.19,24.56 24.19,24.87 24.29,24.97 24.5,24.97 24.6,24.87 24.6,24.56 24.7,24.46 24.9,24.46 25.01,24.56 25.01,25.23 25.12,25.35 25.29,25.35 25.41,25.23 25.41,24.56 25.51,24.46 25.74,24.46 25.84,24.56 25.84,24.74 25.94,24.84 26.15,24.84 26.25,24.74 26.25,24.56 26.35,24.46 26.52,24.46 26.9,24.08 28.09,24.08 28.63,24.62 29.64,24.62 29.77,24.49 30.54,24.49 30.68,24.35 30.68,24.21 30.81,24.08 31.06,24.08 31.32,24.34 31.57,24.34 31.83,24.08 32.08,24.08 32.33,24.34 32.59,24.34 32.72,24.21 TP1MA8.1
  BOTTOM w0.102: 46.6,24.48 47.31,24.48
  BOTTOM w0.127: 47.31,24.48 47.52,24.26 47.74,24.26 48.35,24.87 49.91,24.87 50.85,25.81 51.44,25.81 51.54,25.71 51.54,25.61 51.64,25.5 51.84,25.5 51.95,25.61 51.95,25.71 52.05,25.81 52.32,25.81 52.58,25.55 53.45,25.55 53.75,25.85 55.71,25.85 56.16,26.29 57.1,26.29 57.23,26.16 57.23,25.96 57.1,25.83 56.97,25.83 56.85,25.71 56.85,25.43 56.97,25.3 57.25,25.3 57.4,25.45 TP1MC6.1 58.12,25.83 58.45,25.83 59.05,26.44 61.44,26.44 62.03,27.03 62.48,27.03 62.85,27.4 63.19,27.4 63.6,27 RN13.3 ; v2(23.44,29.16) 23.09,29.16 22.96,29.29 22.96,29.92 23.09,30.05 24.54,30.05 24.66,30.18 24.66,36.53 30.53,42.4 31.09,42.4 31.32,42.62 31.32,43.18 34.09,45.95 34.39,45.95 34.49,46.05 34.49,46.36 34.66,46.52 35.32,46.52 35.48,46.69 35.48,47.35 35.71,47.58 36.14,47.58 36.4,47.83 38.81,47.83 39.07,47.58 39.07,47.3 39.19,47.17 39.4,47.17 39.52,47.3 39.52,47.46 39.64,47.58 39.81,47.58 39.93,47.46 39.93,46.92 40.03,46.81 40.23,46.81 40.34,46.92 40.34,47.46 40.45,47.58 40.62,47.58 40.74,47.46 40.74,46.92 40.84,46.81 41.05,46.81 41.15,46.92 41.15,47.46 41.27,47.58 41.44,47.58 41.55,47.46 41.55,46.92 41.66,46.81 41.86,46.81 41.96,46.92 41.96,47.46 42.08,47.58 42.25,47.58 42.37,47.46 42.37,46.92 42.47,46.81 42.67,46.81 42.77,46.92 42.77,47.46 42.89,47.58 43.06,47.58 43.18,47.46 43.18,46.92 43.28,46.81 43.51,46.81 43.64,46.94 43.64,47.45 43.76,47.58 43.97,47.58 44.09,47.45 44.09,47.32 44.22,47.2 44.52,47.2 49.94,52.62 55.52,52.62 56.93,54.03 58.55,54.03 58.94,54.42 59.53,54.42 v1(59.94,54) ; 46.6,24.48 46.33,24.21 TP1MB8.1 45.34,24.74 43.92,24.74 43.36,25.3 42.82,25.3 42.58,25.54 42.58,25.87 42.34,26.11 40.92,26.11 40.59,25.78 39.8,25.78 39.5,25.48 37.72,25.48 37.08,24.84 35.62,24.84 35.19,24.41 34.77,24.41 34.7,24.49 33.45,24.49 TP1MA8.1
H_DDR1_A11: length 112.5
  TOP w0.102: v1(59.13,52.4) U52.AD22 ; U65.R7 TP1MA18.1
  TOP w0.127: TP1MC20.1 U67.M7 ; U66.R7 TP1MB18.1
  L3-SIGNAL w0.102: 58.87,52.4 58.52,52.05 57.38,52.05
  L3-SIGNAL w0.114: 57.38,52.05 55.78,50.45 49.05,50.45 42.37,43.77 36.27,43.77 31.95,39.45 31.19,39.45 29.64,37.9 29.64,37.75 29.75,37.64 29.75,37.5 29.6,37.35 29.46,37.35 29.35,37.46 29.21,37.46 29.06,37.32 29.06,37.18 29.17,37.07 29.17,36.92 29.03,36.78 28.89,36.78 28.77,36.89 28.63,36.89 28.49,36.74 28.49,36.6 28.6,36.49 28.6,36.35 28.45,36.2 28.31,36.2 28.2,36.31 28.06,36.31 27.91,36.17 27.91,36.03 28.02,35.92 28.02,35.77 27.88,35.63 27.74,35.63 27.62,35.74 27.48,35.74 27.34,35.59 27.34,35.45 27.45,35.34 27.45,35.2 27.3,35.05 27.16,35.05 27.05,35.16 26.91,35.16 26.49,34.75 24.66,34.75 22.17,32.26 22.17,29.88 22.3,29.75 22.82,29.75 22.94,29.64 22.94,29.47 22.82,29.35 22.29,29.35 22.17,29.23 22.17,29.06 22.29,28.94 22.82,28.94 22.94,28.82 22.94,28.65 22.82,28.54 22.29,28.54 22.17,28.42 22.17,28.25 22.29,28.13 22.82,28.13 22.94,28.01 22.94,27.61 22.81,27.49 22,27.49 21.87,27.36 21.87,23.45 23.44,21.87 23.79,21.87 24.08,21.59 24.08,21.08 24.21,20.96 27,20.96 27.13,21.08 27.13,21.54 27.29,21.71 28.61,21.71 29.03,21.29 30.73,21.29 30.86,21.41 30.86,21.78 30.99,21.9 31.96,21.9 32.48,21.39 33.98,21.39 TP1MA18.1 34.65,21.33 40.32,21.33 40.74,20.91 41.23,20.91 41.81,21.5 42.63,21.5 42.82,21.31 43.71,21.31 44.18,21.78 46.42,21.78 46.51,21.69 TP1MB18.1 ; v1(59.13,52.4) 58.87,52.4
  BOTTOM w0.127: RN17.4 63.49,20.71 63.09,21.11 62.1,21.11 61.9,20.91 61.14,20.91 60.99,21.06 60.12,21.06 59.33,21.85 58.64,21.85 TP1MC20.1 57.76,21.45 57.63,21.33 57.63,20.91 57.51,20.78 56.92,20.78 56.82,20.88 56.82,21.32 56.7,21.44 56.54,21.44 56.42,21.32 56.42,20.91 56.29,20.78 55.6,20.78 55.47,20.91 55.47,21.29 55.35,21.41 54.87,21.41 54.77,21.31 54.77,21.17 54.65,21.06 53.14,21.06 52.98,20.91 50.98,20.91 50.32,21.57 49.58,21.57 49.31,21.3 47.92,21.3 47.52,21.69 TP1MB18.1
H_DDR1_A12: length 127.8
  TOP w0.102: v1(59.94,53.2) U52.AC21
  TOP w0.127: U66.N7 46.58,22.6 46.46,22.48 46.33,22.48 46.2,22.35 46.2,22.08 46.08,21.95 45.87,21.95 45.75,22.08 TP1MB13.1 ; U65.N7 33.88,22.6 33.76,22.48 33.63,22.48 33.5,22.35 33.5,22.08 33.38,21.95 33.17,21.95 33.05,22.08 TP1MA13.1 ; TP1MC15.1 U67.K7
  L3-SIGNAL w0.114: TP1MA13.1 33.3,22.88 36.82,22.88 37.4,23.46 42.02,23.46 42.27,23.22 44.78,23.22 45.37,22.63 TP1MB13.1
  BOTTOM w0.127: RN15.1 63.6,22.5 63.18,22.08 62.76,22.08 62.48,22.35 59.52,22.35 58.83,23.05 TP1MC15.1 56.45,23.05 56.06,22.66 51.69,22.66 51.61,22.74 51.61,23.07 51.51,23.17 51.31,23.17 51.21,23.07 51.21,22.7 51.09,22.58 50.92,22.58 50.8,22.7 50.8,23.07 50.7,23.17 50.5,23.17 50.39,23.07 50.39,22.74 50.29,22.63 50.09,22.63 49.9,22.45 49.1,22.45 48.72,22.08 48.39,22.08 47.96,22.51 46.25,22.51 46.13,22.63 TP1MB13.1 ; v1(59.94,53.2) 59.51,52.83 57.25,52.83 55.96,51.54 53.98,51.54 53.57,51.13 50.18,51.13 41.98,42.93 41.83,42.93 41.69,43.07 41.55,43.07 41.4,42.93 41.4,42.78 41.55,42.64 41.55,42.5 41.4,42.35 41.26,42.35 41.11,42.5 40.97,42.5 40.83,42.35 40.83,42.21 40.97,42.06 40.97,41.92 40.79,41.73 40.46,41.73 40.34,41.86 40.34,42.24 40.21,42.37 39.34,42.37 39.22,42.5 39.22,42.89 39.1,43 38.93,43 38.81,42.89 38.81,42.49 38.69,42.37 38.52,42.37 38.4,42.49 38.4,42.89 38.29,43 38.12,43 38,42.89 38,42.49 37.88,42.37 37.71,42.37 37.59,42.49 37.59,42.89 37.47,43 37.3,43 37.19,42.89 37.19,42.49 37.07,42.37 36.9,42.37 36.78,42.49 36.78,42.89 36.66,43 36.49,43 36.37,42.89 36.37,42.49 36.25,42.37 36.09,42.37 35.97,42.49 35.97,42.89 35.85,43 35.68,43 35.56,42.89 35.56,42.49 35.44,42.37 35.27,42.37 35.15,42.49 35.15,42.89 35.03,43 34.87,43 34.75,42.89 34.75,42.49 34.63,42.37 34.46,42.37 34.21,42.62 33.6,42.62 33.48,42.5 33.48,40.85 33.35,40.72 32.46,40.72 31.43,39.69 31.29,39.69 30.61,40.37 30.46,40.37 30.32,40.23 30.32,40.09 31,39.4 31,39.26 30.86,39.12 30.71,39.12 30.03,39.8 29.89,39.8 29.74,39.65 29.74,39.51 30.43,38.83 30.43,38.68 30.28,38.54 30.14,38.54 29.46,39.22 29.31,39.22 29.17,39.08 29.17,38.93 29.85,38.25 29.85,38.11 29.71,37.97 29.56,37.97 28.88,38.65 28.74,38.65 28.59,38.5 28.59,38.36 29.28,37.68 29.28,37.53 29.13,37.39 28.99,37.39 28.31,38.07 28.16,38.07 27.67,37.58 27.67,37.4 27.83,37.24 28.01,37.24 28.2,37.44 28.38,37.44 28.69,37.13 28.69,36.95 28.4,36.65 27.78,36.65 27.33,37.1 27.19,37.1 27.05,36.95 27.05,36.81 27.35,36.51 27.35,36.37 26.62,35.64 26.62,35.49 26.52,35.39 26.34,35.39 26.24,35.29 26.24,35.08 26.34,34.98 26.52,34.98 26.62,34.88 26.62,34.68 26.52,34.57 26.34,34.57 26.24,34.47 26.24,34.27 26.34,34.17 26.52,34.17 26.62,34.07 26.62,33.86 26.52,33.76 26.34,33.76 26.24,33.66 26.24,33.46 26.34,33.36 26.52,33.36 26.62,33.25 26.62,33.05 26.52,32.95 26.34,32.95 26.24,32.85 26.24,32.64 26.34,32.54 26.52,32.54 26.62,32.44 26.62,32.24 26.52,32.14 26.34,32.14 26.24,32.03 26.24,31.83 26.34,31.73 26.52,31.73 26.62,31.63 26.62,31.43 26.52,31.32 26.28,31.32 26.16,31.2 26.16,31.04 26.28,30.92 26.52,30.92 26.62,30.82 26.62,30.56 26.09,30.03 26.09,28.99 25.48,28.38 25.48,25.61 25.6,25.48 26.11,25.48 26.24,25.35 26.24,24.84 26.37,24.72 27,24.72 27.13,24.59 27.13,24.08 27.25,23.96 27.39,23.96 27.51,24.08 27.51,24.72 27.63,24.84 27.77,24.84 27.89,24.72 27.89,24.08 28.01,23.96 28.15,23.96 28.27,24.08 28.27,24.36 28.4,24.49 28.96,24.49 29.08,24.36 29.08,23.75 29.21,23.62 31.72,23.62 32.72,22.63 TP1MA13.1
